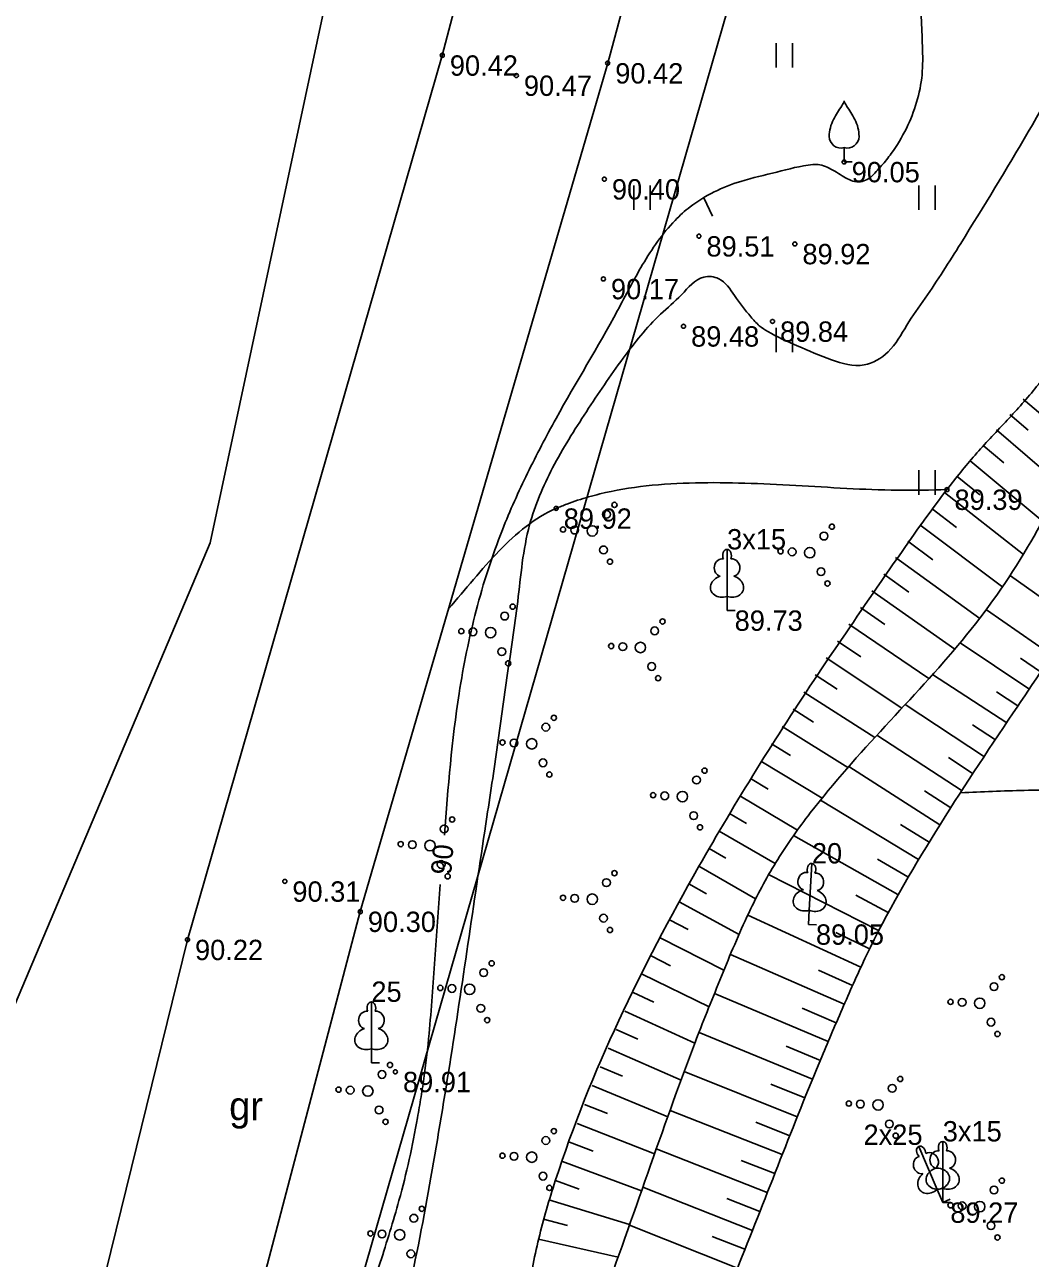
# Model space of a CAD drawing. Extents: x 635228 to 635525, y 248590 to 248800.
# Drawn here: x 635336.53 to 635361.24, y 248708.73 to 248739.05 of the extents above; entities that cross this region are included whole.
import ezdxf

# ---------------------------------------------------------------- set-up
doc = ezdxf.new("R2010")
doc.units = 0
for name, color, linetype in [('CELI_CMAL_####_####_#', 7, 'Continuous'), ('CELI_CSEG_####_TKST_#', 7, 'Continuous'), ('RAMI_UZMR_####_####_#', 7, 'Continuous'), ('RELJ_AATZ_####_TKST_#', 7, 'Continuous'), ('RELJ_ELEM_####_####_#', 7, 'Continuous'), ('RELJ_HORZ_####_TKST_#', 7, 'Continuous'), ('RELJ_HORZ_PAMT_####_#', 7, 'Continuous'), ('RELJ_HORZ_RESN_####_#', 7, 'Continuous'), ('RELJ_NOGA_####_####_#', 7, 'Continuous'), ('RELJ_NOGL_####_####_#', 7, 'Continuous'), ('ROBZ_PROJ_####_####_#', 7, 'Continuous'), ('ROBZ_UZMR_####_####_#', 7, 'Continuous'), ('TERT_DIAM_####_TKST_#', 7, 'Continuous'), ('TERT_ELEM_####_####_#', 7, 'Continuous'), ('TERT_KONT_####_####_#', 7, 'Continuous')]:
    doc.layers.add(name, color=color, linetype=linetype)

msp = doc.modelspace()

# ---------------------------------------------------------------- linework, layer by layer
at = {"layer": 'CELI_CMAL_####_####_#'}
for points in [[(635327.703, 248680.035), (635336.747, 248691.797), (635341.71, 248705.602), (635344.776, 248717.251), (635350.856, 248738.106), (635354.904, 248753.168), (635356.755, 248761.086), (635356.988, 248762.081)], [(635352.126, 248761.775), (635351.394, 248755.812), (635346.791, 248738.298), (635340.529, 248716.56), (635338.144, 248706.864), (635332.779, 248692.762), (635327.977, 248685.285), (635325.201, 248682.696)]]:
    msp.add_lwpolyline(points, dxfattribs=at)
at = {"layer": 'RAMI_UZMR_####_####_#'}
msp.add_lwpolyline([(635379.918, 248627.738), (635364.657, 248634.365), (635359.326, 248636.387), (635355.893, 248639.014), (635323.971, 248655.917), (635326.8, 248663.851), (635331.354, 248676.262), (635327.703, 248680.035), (635326.374, 248681.182), (635325.201, 248682.696), (635327.977, 248685.285), (635332.779, 248692.762), (635338.144, 248706.864), (635340.529, 248716.56), (635346.791, 248738.298), (635351.394, 248755.812), (635352.126, 248761.775)], dxfattribs=at)
at = {"layer": 'RELJ_ELEM_####_####_#'}
for centre in [(635346.791, 248738.298), (635350.856, 248738.106), (635348.611, 248737.802), (635356.667, 248735.678), (635350.775, 248735.255), (635353.097, 248733.853), (635355.456, 248733.663), (635350.751, 248732.803), (635354.906, 248731.758), (635352.72, 248731.639), (635359.193, 248727.625), (635349.59, 248727.162), (635342.921, 248717.995), (635344.776, 248717.251), (635340.529, 248716.56), (635345.64, 248713.314)]:
    msp.add_circle(centre, 0.05, dxfattribs=at)
at = {"layer": 'RELJ_HORZ_PAMT_####_#'}
msp.add_spline([(635330.297, 248677.354), (635331.177, 248678.319), (635332.06, 248679.489), (635332.793, 248680.772), (635333.481, 248682.089), (635334.226, 248683.36), (635335.284, 248684.77), (635336.431, 248686.125), (635337.538, 248687.508), (635338.035, 248688.237), (635338.472, 248689.004), (635339.583, 248691.554), (635340.487, 248694.188), (635341.335, 248696.84), (635341.787, 248698.153), (635342.281, 248699.447), (635343.206, 248701.423), (635344.222, 248703.369), (635345.157, 248705.345), (635345.54, 248706.364), (635345.837, 248707.412), (635346.445, 248710.352), (635346.944, 248713.307), (635347.835, 248719.233), (635348.116, 248721.113), (635348.378, 248722.995), (635348.645, 248724.878), (635348.937, 248726.758), (635349.503, 248728.159), (635350.332, 248729.539), (635351.235, 248730.852), (635351.672, 248731.412), (635352.153, 248731.934), (635352.67, 248732.415), (635353.216, 248732.849), (635353.585, 248732.808), (635353.973, 248732.393), (635354.375, 248731.871), (635354.581, 248731.654), (635354.79, 248731.511), (635355.514, 248731.162), (635356.357, 248730.815), (635357.156, 248730.69), (635357.748, 248731.008), (635358.207, 248731.666), (635358.657, 248732.33), (635359.531, 248733.675), (635361.193, 248736.42), (635362.771, 248739.216), (635364.301, 248742.038), (635372.089, 248756.526)], degree=3, dxfattribs=at)
at = {"layer": 'RELJ_HORZ_RESN_####_#'}
msp.add_line((635353.216, 248734.798), (635353.435, 248734.349), dxfattribs=at)
for points in [[(635358.825, 248747.654), (635358.21, 248746.207), (635357.892, 248744.91), (635357.912, 248743.531), (635358.021, 248742.809), (635358.155, 248742.09), (635358.292, 248741.37), (635358.408, 248740.649), (635358.559, 248739.236), (635358.591, 248738.526), (635358.581, 248737.819), (635358.196, 248736.504), (635357.825, 248735.885), (635357.587, 248735.587), (635357.454, 248735.441), (635357.311, 248735.297), (635356.977, 248735.19), (635356.617, 248735.341), (635356.249, 248735.549), (635356.069, 248735.611), (635355.895, 248735.612), (635355.014, 248735.429), (635354.125, 248735.201), (635352.879, 248734.574), (635352.692, 248734.418), (635352.512, 248734.242), (635351.714, 248733.154), (635351.096, 248732.023), (635349.587, 248729.373), (635348.887, 248728.028), (635348.565, 248727.339), (635348.268, 248726.636), (635347.624, 248724.653), (635347.206, 248722.617), (635346.842, 248719.134)], [(635346.739, 248717.915), (635346.608, 248716.083), (635346.466, 248714.252), (635346.348, 248713.214), (635346.269, 248712.697), (635346.182, 248712.182), (635345.98, 248711.16), (635345.727, 248710.151), (635345.266, 248708.625), (635344.77, 248707.113), (635344.229, 248705.619), (635343.634, 248704.146), (635343.044, 248702.77), (635342.451, 248701.393), (635341.838, 248700.031), (635341.518, 248699.356), (635341.19, 248698.685), (635340.494, 248697.382), (635339.719, 248696.124), (635339.299, 248695.519), (635338.859, 248694.931), (635337.907, 248693.816), (635337.205, 248693.072)]]:
    msp.add_spline(points, degree=3, dxfattribs=at)
at = {"layer": 'RELJ_NOGA_####_####_#'}
for p, q in [((635361.064, 248729.849), (635362.468, 248728.653)), ((635360.738, 248729.47), (635361.185, 248729.085)), ((635360.412, 248729.091), (635361.99, 248727.731)), ((635360.086, 248728.711), (635360.588, 248728.284)), ((635359.764, 248728.329), (635361.532, 248726.858)), ((635359.446, 248727.943), (635360.005, 248727.494)), ((635359.135, 248727.551), (635361.078, 248726.033)), ((635358.829, 248727.156), (635359.429, 248726.696)), ((635358.527, 248726.758), (635360.564, 248725.223)), ((635358.228, 248726.357), (635358.846, 248725.9)), ((635357.932, 248725.954), (635360, 248724.456)), ((635357.639, 248725.548), (635358.256, 248725.106)), ((635362.348, 248724.374), (635360.755, 248725.508)), ((635357.35, 248725.14), (635359.387, 248723.706)), ((635357.065, 248724.73), (635357.666, 248724.313)), ((635361.772, 248723.557), (635360.163, 248724.668)), ((635356.782, 248724.318), (635358.751, 248722.982)), ((635356.502, 248723.903), (635357.078, 248723.518)), ((635361.209, 248722.73), (635359.518, 248723.861)), ((635356.225, 248723.487), (635358.087, 248722.256)), ((635361.489, 248723.144), (635360.997, 248723.481)), ((635355.951, 248723.069), (635356.492, 248722.717)), ((635360.662, 248721.893), (635358.838, 248723.079)), ((635355.68, 248722.649), (635357.423, 248721.534)), ((635360.934, 248722.313), (635360.407, 248722.657)), ((635355.412, 248722.227), (635355.914, 248721.908)), ((635360.113, 248721.057), (635358.165, 248722.341)), ((635355.146, 248721.804), (635356.76, 248720.795)), ((635360.388, 248721.475), (635359.823, 248721.845)), ((635359.564, 248720.222), (635357.473, 248721.589)), ((635354.882, 248721.379), (635355.348, 248721.091)), ((635354.621, 248720.952), (635356.123, 248720.041)), ((635359.838, 248720.639), (635359.233, 248721.038)), ((635359.021, 248719.382), (635356.778, 248720.815)), ((635354.362, 248720.524), (635354.798, 248720.262)), ((635354.106, 248720.095), (635355.52, 248719.256)), ((635358.492, 248718.533), (635356.082, 248719.99)), ((635359.291, 248719.803), (635358.642, 248720.224)), ((635353.851, 248719.665), (635354.267, 248719.421)), ((635358.754, 248718.959), (635358.055, 248719.393)), ((635353.599, 248719.233), (635354.971, 248718.434)), ((635357.987, 248717.67), (635355.423, 248719.119)), ((635353.348, 248718.801), (635353.76, 248718.563)), ((635358.236, 248718.104), (635357.49, 248718.542)), ((635353.099, 248718.367), (635354.491, 248717.57)), ((635357.514, 248716.789), (635354.81, 248718.166)), ((635352.854, 248717.931), (635353.283, 248717.691)), ((635357.746, 248717.232), (635356.955, 248717.658)), ((635352.613, 248717.493), (635354.088, 248716.691)), ((635352.378, 248717.052), (635352.834, 248716.813)), ((635357.081, 248715.888), (635354.3, 248717.165)), ((635357.293, 248716.341), (635356.465, 248716.736)), ((635352.147, 248716.608), (635353.711, 248715.809)), ((635351.922, 248716.162), (635352.403, 248715.921)), ((635356.671, 248714.976), (635353.876, 248716.2)), ((635356.874, 248715.433), (635356.038, 248715.81)), ((635351.701, 248715.713), (635353.347, 248714.914)), ((635351.485, 248715.262), (635351.991, 248715.023)), ((635356.275, 248714.057), (635353.477, 248715.238)), ((635351.274, 248714.809), (635352.998, 248714.015)), ((635356.471, 248714.517), (635355.632, 248714.879)), ((635351.068, 248714.354), (635351.596, 248714.116)), ((635355.891, 248713.134), (635353.101, 248714.282)), ((635350.866, 248713.896), (635352.661, 248713.111)), ((635356.082, 248713.596), (635355.243, 248713.946)), ((635350.668, 248713.437), (635351.217, 248713.205)), ((635355.515, 248712.207), (635352.737, 248713.319)), ((635355.702, 248712.671), (635354.866, 248713.009)), ((635350.475, 248712.976), (635352.333, 248712.211)), ((635350.287, 248712.513), (635350.852, 248712.286)), ((635355.146, 248711.278), (635352.389, 248712.367)), ((635350.102, 248712.048), (635352.009, 248711.301)), ((635355.33, 248711.743), (635354.5, 248712.073)), ((635349.921, 248711.582), (635350.499, 248711.36)), ((635354.779, 248710.348), (635352.051, 248711.421)), ((635349.744, 248711.114), (635351.688, 248710.393)), ((635354.962, 248710.813), (635354.139, 248711.137)), ((635349.571, 248710.645), (635350.157, 248710.43)), ((635354.413, 248709.417), (635351.718, 248710.477)), ((635349.413, 248710.171), (635351.395, 248709.563)), ((635354.596, 248709.882), (635353.783, 248710.202)), ((635349.277, 248709.69), (635349.871, 248709.534)), ((635354.045, 248708.488), (635351.389, 248709.545)), ((635349.159, 248709.204), (635351.111, 248708.762)), ((635354.229, 248708.952), (635353.427, 248709.27))]:
    msp.add_line(p, q, dxfattribs=at)
for points in [[(635375.27, 248754.857), (635369.314, 248744.971), (635367.429, 248741.507), (635365.696, 248737.957), (635363.943, 248734.417), (635363.006, 248732.681), (635362, 248730.984), (635361.355, 248730.103), (635360.628, 248729.283), (635359.885, 248728.474), (635359.193, 248727.625), (635357.58, 248725.368), (635356.018, 248723.079), (635353.089, 248718.349), (635349.569, 248710.638), (635349.163, 248709.221), (635348.864, 248707.772), (635348.539, 248706.335), (635348.053, 248704.954), (635343.12, 248694.162), (635337.407, 248681.667), (635331.093, 248670.147), (635326.8, 248663.851)], [(635326.8, 248663.851), (635325.31, 248661.345), (635325.174, 248660.918), (635325.219, 248660.451), (635325.416, 248659.984), (635325.736, 248659.553), (635326.126, 248659.27), (635326.575, 248659.146), (635327.409, 248659.333), (635327.907, 248659.688), (635328.397, 248660.078), (635328.864, 248660.506), (635329.288, 248660.978), (635331.594, 248663.918), (635332.687, 248665.412), (635333.734, 248666.95), (635337.875, 248673.353), (635341.554, 248680.001), (635347.428, 248693.006), (635353.063, 248706.101), (635354.098, 248708.621), (635355.097, 248711.155), (635356.117, 248713.682), (635356.653, 248714.935), (635357.216, 248716.179), (635358.916, 248719.218), (635360.822, 248722.14), (635362.339, 248724.363), (635363.916, 248726.545), (635365.467, 248728.744), (635366.906, 248731.015), (635368.464, 248733.981), (635369.863, 248737.03), (635371.249, 248740.086), (635372.769, 248743.072), (635378.435, 248753.196)]]:
    msp.add_spline(points, degree=3, dxfattribs=at)
at = {"layer": 'RELJ_NOGL_####_####_#'}
msp.add_spline([(635326.936, 248660.713), (635331.766, 248667.928), (635333.88, 248671.254), (635335.853, 248674.668), (635337.706, 248678.153), (635339.464, 248681.691), (635342.12, 248687.391), (635344.65, 248693.14), (635347.108, 248698.916), (635349.548, 248704.698), (635350.777, 248707.84), (635351.91, 248711.022), (635353.067, 248714.195), (635353.692, 248715.764), (635354.368, 248717.312), (635355.034, 248718.536), (635355.835, 248719.677), (635357.677, 248721.811), (635359.567, 248723.919), (635361.176, 248726.206), (635362.355, 248728.434), (635362.939, 248729.551), (635363.546, 248730.656), (635367.422, 248737.348), (635371.307, 248744.035), (635372.506, 248746.487), (635373.579, 248749.023), (635374.785, 248751.459), (635376.384, 248753.612), (635376.807, 248754.05)], degree=3, dxfattribs=at)
at = {"layer": 'ROBZ_PROJ_####_####_#'}
msp.add_lwpolyline([(635363.321, 248797.676), (635360.888, 248769.918), (635360.483, 248762.615), (635343.343, 248703.12), (635337.46, 248688.66), (635327.79, 248676.828), (635329.653, 248676.366), (635325.542, 248659.74), (635315.4, 248665.602), (635272.581, 248690.35), (635264.056, 248694.511), (635270.042, 248696.015), (635282.096, 248694.845), (635298.597, 248686.068), (635311.236, 248680.45), (635322.498, 248682.379), (635341.086, 248726.313), (635346.481, 248751.583), (635353.471, 248778.803), (635354.805, 248797.676)], dxfattribs=at)
at = {"layer": 'ROBZ_UZMR_####_####_#'}
msp.add_lwpolyline([(635325.542, 248659.74), (635329.653, 248676.366), (635327.79, 248676.828), (635337.46, 248688.66), (635343.343, 248703.12), (635360.483, 248762.615), (635458.607, 248711.134), (635465.459, 248707.539), (635439.457, 248681.038), (635424.543, 248670.014), (635420.979, 248667.379), (635407.07, 248653.18), (635400.067, 248641.149), (635395.162, 248617.539), (635389.031, 248621.062), (635375.858, 248629.115)], close=True, dxfattribs=at)
at = {"layer": 'TERT_ELEM_####_####_#'}
for p, q in [((635355, 248738), (635355, 248738.6)), ((635355.4, 248738), (635355.4, 248738.6)), ((635356.667, 248736.03), (635356.667, 248735.678)), ((635356.667, 248735.678), (635356.867, 248735.678)), ((635351.5, 248734.5), (635351.5, 248735.1)), ((635351.9, 248734.5), (635351.9, 248735.1)), ((635358.5, 248734.5), (635358.5, 248735.1)), ((635358.9, 248734.5), (635358.9, 248735.1)), ((635355, 248731), (635355, 248731.6)), ((635355.4, 248731), (635355.4, 248731.6)), ((635358.5, 248727.5), (635358.5, 248728.1)), ((635358.9, 248727.5), (635358.9, 248728.1)), ((635353.79, 248725.001), (635353.79, 248724.654)), ((635353.79, 248724.654), (635353.99, 248724.654)), ((635355.808, 248717.284), (635355.788, 248716.938)), ((635355.788, 248716.938), (635355.988, 248716.927)), ((635345.049, 248713.881), (635345.049, 248713.534)), ((635345.049, 248713.534), (635345.249, 248713.534)), ((635358.953, 248710.422), (635359.09, 248710.103)), ((635359.09, 248710.45), (635359.09, 248710.103)), ((635359.09, 248710.103), (635359.274, 248710.182)), ((635359.09, 248710.103), (635359.29, 248710.103))]:
    msp.add_line(p, q, dxfattribs=at)
for points in [[(635353.79, 248726.154), (635353.79, 248725.001)], [(635353.88, 248725.922), (635353.879, 248725.923)], [(635355.873, 248718.436), (635355.808, 248717.284)], [(635355.949, 248718.199), (635355.948, 248718.2)], [(635345.049, 248715.034), (635345.049, 248713.881)], [(635345.139, 248714.802), (635345.138, 248714.803)], [(635358.499, 248711.482), (635358.953, 248710.422)], [(635359.09, 248711.603), (635359.09, 248710.45)], [(635358.673, 248711.303), (635358.672, 248711.304)], [(635359.18, 248711.371), (635359.179, 248711.372)]]:
    msp.add_lwpolyline(points, dxfattribs=at)
for centre, radius in [((635351.022, 248727.248), 0.064), ((635350.825, 248727.016), 0.096), ((635349.759, 248726.643), 0.064), ((635350.044, 248726.63), 0.096), ((635350.478, 248726.609), 0.128), ((635356.366, 248726.713), 0.064), ((635356.17, 248726.482), 0.096), ((635350.754, 248726.142), 0.096), ((635355.104, 248726.108), 0.064), ((635355.388, 248726.095), 0.096), ((635355.822, 248726.074), 0.128), ((635350.912, 248725.853), 0.064), ((635356.099, 248725.607), 0.096), ((635356.256, 248725.318), 0.064), ((635348.522, 248724.748), 0.064), ((635348.325, 248724.516), 0.096), ((635347.259, 248724.143), 0.064), ((635347.544, 248724.13), 0.096), ((635347.978, 248724.109), 0.128), ((635352.009, 248724.152), 0.096), ((635352.205, 248724.384), 0.064), ((635348.254, 248723.642), 0.096), ((635350.943, 248723.779), 0.064), ((635351.227, 248723.765), 0.096), ((635351.661, 248723.744), 0.128), ((635348.412, 248723.353), 0.064), ((635351.938, 248723.277), 0.096), ((635352.095, 248722.988), 0.064), ((635349.336, 248721.784), 0.096), ((635349.533, 248722.016), 0.064), ((635348.555, 248721.397), 0.096), ((635348.989, 248721.376), 0.128), ((635348.27, 248721.411), 0.064), ((635349.265, 248720.91), 0.096), ((635349.423, 248720.62), 0.064), ((635353.039, 248720.486), 0.096), ((635353.236, 248720.717), 0.064), ((635351.973, 248720.112), 0.064), ((635352.258, 248720.099), 0.096), ((635352.692, 248720.078), 0.128), ((635352.968, 248719.611), 0.096), ((635346.836, 248719.284), 0.096), ((635347.033, 248719.516), 0.064), ((635353.126, 248719.322), 0.064), ((635345.77, 248718.911), 0.064), ((635346.055, 248718.897), 0.096), ((635346.489, 248718.876), 0.128), ((635346.765, 248718.41), 0.096), ((635346.923, 248718.12), 0.064), ((635351.022, 248718.197), 0.064), ((635350.825, 248717.965), 0.096), ((635349.759, 248717.591), 0.064), ((635350.044, 248717.578), 0.096), ((635350.478, 248717.557), 0.128), ((635350.754, 248717.09), 0.096), ((635350.912, 248716.801), 0.064), ((635348.006, 248715.981), 0.064), ((635347.809, 248715.75), 0.096), ((635346.743, 248715.376), 0.064), ((635347.028, 248715.363), 0.096), ((635347.462, 248715.342), 0.128), ((635360.348, 248715.408), 0.096), ((635360.544, 248715.639), 0.064), ((635359.566, 248715.021), 0.096), ((635360, 248715), 0.128), ((635347.738, 248714.875), 0.096), ((635359.282, 248715.034), 0.064), ((635347.896, 248714.586), 0.064), ((635360.276, 248714.533), 0.096), ((635360.434, 248714.244), 0.064), ((635345.309, 248713.25), 0.096), ((635345.506, 248713.481), 0.064), ((635357.848, 248712.908), 0.096), ((635358.044, 248713.139), 0.064), ((635344.243, 248712.876), 0.064), ((635344.528, 248712.863), 0.096), ((635344.962, 248712.842), 0.128), ((635345.238, 248712.375), 0.096), ((635356.782, 248712.534), 0.064), ((635357.066, 248712.521), 0.096), ((635357.5, 248712.5), 0.128), ((635345.396, 248712.086), 0.064), ((635357.776, 248712.033), 0.096), ((635349.533, 248711.857), 0.064), ((635357.934, 248711.744), 0.064), ((635349.336, 248711.625), 0.096), ((635348.27, 248711.252), 0.064), ((635348.555, 248711.238), 0.096), ((635348.989, 248711.217), 0.128), ((635349.265, 248710.75), 0.096), ((635360.544, 248710.639), 0.064), ((635349.423, 248710.461), 0.064), ((635360.348, 248710.408), 0.096), ((635346.288, 248709.947), 0.064), ((635359.282, 248710.034), 0.064), ((635359.566, 248710.021), 0.096), ((635360, 248710), 0.128), ((635346.091, 248709.715), 0.096), ((635345.026, 248709.342), 0.064), ((635345.31, 248709.329), 0.096), ((635345.744, 248709.308), 0.128), ((635360.276, 248709.533), 0.096), ((635360.434, 248709.244), 0.064), ((635346.02, 248708.841), 0.096)]:
    msp.add_circle(centre, radius, dxfattribs=at)
for centre, radius, start, end in [((635369.292, 248729.282), 14.88, 148.4844, 149.9901), ((635356.25, 248737.316), 0.439, 324.3837, 341.712), ((635357.084, 248737.316), 0.439, 198.288, 215.6163), ((635344.042, 248729.282), 14.88, 30.0099, 31.5156), ((635357.191, 248736.303), 0.89, 151.757, 179.9138), ((635356.143, 248736.303), 0.89, 0.0862, 28.243), ((635356.591, 248736.309), 0.29, 181.0782, 285.2823), ((635356.743, 248736.309), 0.29, 254.7177, 358.9218)]:
    msp.add_arc(centre, radius, start, end, dxfattribs=at)
for centre, major_axis, ratio, start_param, end_param in [((635353.79, 248726.004), (0, -0.15), 0.707107, 3.14537, 5.287485), ((635353.79, 248726.004), (0, -0.15), 0.707107, 0.995701, 3.137816), ((635353.662, 248725.709), (-0.039, -0.212), 0.861323, 3.141593, 6.283185), ((635353.918, 248725.709), (0.039, -0.212), 0.861323, 0, 3.141593), ((635353.7, 248725.247), (0.307, 0.095), 0.814445, 1.570796, 4.752015), ((635353.88, 248725.247), (-0.307, 0.095), 0.814445, 1.531171, 4.712389), ((635355.719, 248717.999), (-0.051, -0.21), 0.861323, 3.141593, 6.283185), ((635355.865, 248718.286), (-0.008, -0.15), 0.707107, 3.14537, 5.287485), ((635355.864, 248718.286), (-0.008, -0.15), 0.707107, 0.995701, 3.137816), ((635355.976, 248717.984), (0.027, -0.214), 0.861323, 0, 3.141593), ((635355.732, 248717.535), (0.312, 0.078), 0.814445, 1.570796, 4.752015), ((635355.911, 248717.525), (-0.301, 0.112), 0.814445, 1.531171, 4.712389), ((635344.921, 248714.589), (-0.039, -0.212), 0.861323, 3.141593, 6.283185), ((635345.049, 248714.884), (0, -0.15), 0.707107, 3.14537, 5.287485), ((635345.049, 248714.884), (0, -0.15), 0.707107, 0.995701, 3.137816), ((635345.177, 248714.589), (0.039, -0.212), 0.861323, 0, 3.141593), ((635344.959, 248714.127), (0.307, 0.095), 0.814445, 1.570796, 4.752015), ((635345.139, 248714.127), (-0.307, 0.095), 0.814445, 1.531171, 4.712389), ((635358.558, 248711.344), (0.059, -0.138), 0.707107, 3.14537, 5.287485), ((635358.558, 248711.344), (0.059, -0.138), 0.707107, 0.995701, 3.137816), ((635359.09, 248711.453), (0, -0.15), 0.707107, 3.14537, 5.287485), ((635359.09, 248711.453), (0, -0.15), 0.707107, 0.995701, 3.137816), ((635358.556, 248711.022), (0.048, -0.21), 0.861323, 3.141593, 6.283185), ((635358.792, 248711.123), (0.119, -0.18), 0.861323, 0, 3.141593), ((635358.962, 248711.158), (-0.039, -0.212), 0.861323, 3.141593, 6.283185), ((635359.218, 248711.158), (0.039, -0.212), 0.861323, 0, 3.141593), ((635359, 248710.696), (0.307, 0.095), 0.814445, 1.570796, 4.752015), ((635358.939, 248710.683), (-0.319, -0.033), 0.814445, 1.531171, 4.712389), ((635359.18, 248710.696), (-0.307, 0.095), 0.814445, 1.531171, 4.712389), ((635358.774, 248710.613), (0.245, 0.208), 0.814445, 1.570796, 4.752015)]:
    msp.add_ellipse(centre, major_axis=major_axis, ratio=ratio, start_param=start_param, end_param=end_param, dxfattribs=at)
at = {"layer": 'TERT_KONT_####_####_#'}
for points in [[(635359.193, 248727.625), (635357.974, 248727.61), (635356.729, 248727.655), (635354.224, 248727.782), (635351.802, 248727.714), (635350.662, 248727.517), (635350.117, 248727.361), (635349.851, 248727.268), (635349.72, 248727.216), (635349.59, 248727.162), (635348.853, 248726.721), (635348.186, 248726.117), (635347.56, 248725.419), (635346.946, 248724.693)], [(635373.4, 248711.674), (635373.195, 248712.802), (635373.056, 248714.014), (635372.819, 248716.487), (635372.369, 248718.693), (635371.966, 248719.57), (635371.702, 248719.931), (635371.552, 248720.089), (635371.473, 248720.162), (635371.432, 248720.197), (635371.411, 248720.214), (635371.39, 248720.231), (635371.106, 248720.414), (635370.784, 248720.551), (635370.043, 248720.701), (635368.282, 248720.649), (635366.355, 248720.388), (635365.407, 248720.276), (635364.729, 248720.234), (635364.511, 248720.231), (635362.802, 248720.239), (635361.094, 248720.231), (635359.533, 248720.175)], [(635347.944, 248675.14), (635353.969, 248676.317), (635361.548, 248680.892), (635362.735, 248687.694), (635367.699, 248695.072), (635365.801, 248699.259), (635373.4, 248711.674), (635374.835, 248703.881), (635382.868, 248697.463), (635386.085, 248703.415)]]:
    msp.add_spline(points, degree=3, dxfattribs=at)

# ---------------------------------------------------------------- texts
at = {"layer": 'CELI_CSEG_####_TKST_#'}
msp.add_text('gr', height=0.7, dxfattribs=at).set_placement((635341.554, 248712.125))
at = {"layer": 'RELJ_AATZ_####_TKST_#'}
for s, p in [(' 90.42', (635346.791, 248737.798)), (' 90.42', (635350.856, 248737.606)), (' 90.47', (635348.611, 248737.302)), (' 90.05', (635356.667, 248735.178)), (' 90.40', (635350.775, 248734.755)), (' 89.51', (635353.097, 248733.353)), (' 89.92', (635355.456, 248733.163)), (' 90.17', (635350.751, 248732.303)), (' 89.48', (635352.72, 248731.139)), (' 89.84', (635354.906, 248731.258)), (' 89.39', (635359.193, 248727.125)), (' 89.92', (635349.59, 248726.662)), (' 89.73', (635353.79, 248724.154)), (' 90.31', (635342.921, 248717.495)), (' 90.30', (635344.776, 248716.751)), (' 89.05', (635355.788, 248716.438)), (' 90.22', (635340.529, 248716.06)), (' 89.91', (635345.64, 248712.814)), (' 89.27', (635359.09, 248709.603))]:
    msp.add_text(s, height=0.5, dxfattribs=at).set_placement(p)
at = {"layer": 'RELJ_HORZ_####_TKST_#'}
msp.add_text('90', height=0.5, rotation=85.097, dxfattribs=at).set_placement((635347.007, 248718.143))
at = {"layer": 'TERT_DIAM_####_TKST_#'}
for s, p in [('3x15', (635353.79, 248726.154)), ('20', (635355.873, 248718.436)), ('25', (635345.049, 248715.034)), ('3x15', (635359.09, 248711.603)), ('2x25', (635357.143, 248711.519))]:
    msp.add_text(s, height=0.5, dxfattribs=at).set_placement(p)

doc.saveas('drawing.dxf')
